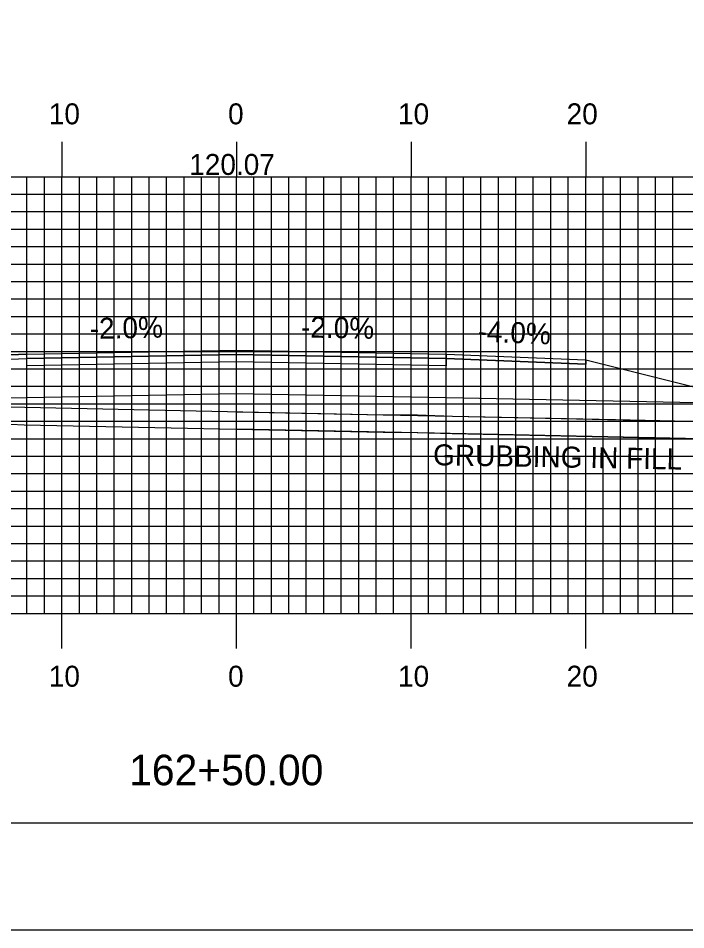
# Model space of a CAD drawing. Extents: x 1780680 to 1781023, y 442591 to 442811.
# Drawn here: x 1780832.9 to 1780871.1, y 442590.5 to 442642.7 of the extents above; entities that cross this region are included whole.
import ezdxf

# ---------------------------------------------------------------- set-up
doc = ezdxf.new("R2010")
doc.units = 0
for name, color, linetype in [('ANNOTATION', 7, 'Continuous'), ('BORDER', 7, 'Continuous'), ('D_Roadway_Centerline', 7, 'Continuous'), ('D_Roadway_Centerline_Text', 7, 'Continuous'), ('D_Roadway_Edge_Shoulder', 7, 'Continuous'), ('D_Roadway_Edge_TW', 7, 'Continuous'), ('D_Roadway_Pavement', 7, 'Continuous'), ('D_Roadway_SlopeLines', 7, 'Continuous'), ('D_Roadway_SubGrade', 7, 'Continuous'), ('GRUBBING IN FILL', 7, 'Continuous'), ('H_V ANNOTATION', 7, 'Continuous'), ('MAJOR', 7, 'Continuous'), ('MINOR', 7, 'Continuous'), ('PLOT BOUNDARY', 7, 'Continuous'), ('S_Roadway_Centerline', 7, 'Continuous')]:
    doc.layers.add(name, color=color, linetype=linetype)

msp = doc.modelspace()

# ---------------------------------------------------------------- linework, layer by layer
at = {"layer": 'BORDER'}
msp.add_lwpolyline([(1780695.782, 442596.665), (1781015.782, 442596.665), (1781015.782, 442806.665), (1780695.782, 442806.665)], close=True, dxfattribs=at)
at = {"layer": 'D_Roadway_Centerline'}
msp.add_lwpolyline([(1780799.726, 442621.091), (1780800.976, 442621.083), (1780802.226, 442621.017), (1780803.476, 442620.894), (1780804.726, 442620.714), (1780811.207, 442619.634), (1780815.207, 442620.634), (1780825.382, 442623.178), (1780833.382, 442623.498), (1780845.382, 442623.738), (1780857.382, 442623.498), (1780865.382, 442623.178), (1780875.556, 442620.634), (1780880.076, 442619.504)], dxfattribs=at)
at = {"layer": 'D_Roadway_Edge_Shoulder'}
for points in [[(1780833.382, 442623.498), (1780825.382, 442623.178), (1780825.382, 442622.928), (1780833.382, 442623.248)], [(1780857.382, 442623.498), (1780865.382, 442623.178), (1780865.382, 442622.928), (1780857.382, 442623.248)]]:
    msp.add_lwpolyline(points, close=True, dxfattribs=at)
at = {"layer": 'D_Roadway_Edge_TW'}
msp.add_lwpolyline([(1780833.382, 442623.248), (1780833.382, 442623.498), (1780845.382, 442623.738), (1780857.382, 442623.498), (1780857.382, 442623.248), (1780845.382, 442623.488)], close=True, dxfattribs=at)
at = {"layer": 'D_Roadway_Pavement'}
msp.add_lwpolyline([(1780833.382, 442622.831), (1780833.382, 442623.248), (1780845.382, 442623.488), (1780857.382, 442623.248), (1780857.382, 442622.831), (1780845.382, 442623.071)], close=True, dxfattribs=at)
at = {"layer": 'D_Roadway_SlopeLines'}
msp.add_lwpolyline([(1780865.382, 442623.178), (1780875.556, 442620.634), (1780880.076, 442619.504)], dxfattribs=at)
at = {"layer": 'D_Roadway_SubGrade'}
msp.add_lwpolyline([(1780833.382, 442620.998), (1780815.207, 442620.634), (1780825.382, 442623.178), (1780825.382, 442622.928), (1780833.382, 442623.248), (1780845.382, 442623.488), (1780857.382, 442623.248), (1780865.382, 442622.928), (1780865.382, 442623.178), (1780875.556, 442620.634), (1780857.382, 442620.998), (1780845.382, 442621.238)], close=True, dxfattribs=at)
at = {"layer": 'GRUBBING IN FILL'}
msp.add_lwpolyline([(1780815.207, 442620.095), (1780831.608, 442619.507), (1780832.443, 442619.493), (1780833.221, 442619.462), (1780853.776, 442619.036), (1780855.733, 442619.025), (1780857.728, 442618.957), (1780875.556, 442618.579)], dxfattribs=at)
msp.add_lwpolyline([(1780815.207, 442620.095), (1780831.608, 442619.507), (1780832.443, 442619.493), (1780833.221, 442619.462), (1780853.776, 442619.036), (1780855.733, 442619.025), (1780857.728, 442618.957), (1780875.556, 442618.579)], dxfattribs=at)
msp.add_lwpolyline([(1780875.556, 442618.579), (1780866.642, 442618.768), (1780856.731, 442618.991), (1780845.382, 442619.21), (1780845.382, 442620.21), (1780853.789, 442620.036), (1780857.756, 442619.957), (1780867.082, 442619.759), (1780875.556, 442619.58)], close=True, dxfattribs=at)
msp.add_lwpolyline([(1780875.556, 442618.579), (1780866.642, 442618.768), (1780856.731, 442618.991), (1780845.382, 442619.21), (1780845.382, 442620.21), (1780853.789, 442620.036), (1780857.756, 442619.957), (1780867.082, 442619.759), (1780875.556, 442619.58)], close=True, dxfattribs=at)
at = {"layer": 'MAJOR'}
for p, q in [((1780835.382, 442635.669), (1780835.382, 442633.665)), ((1780845.382, 442635.669), (1780845.382, 442633.665)), ((1780855.382, 442635.669), (1780855.382, 442633.665)), ((1780865.382, 442635.669), (1780865.382, 442633.665)), ((1780705.382, 442633.665), (1780985.382, 442633.665)), ((1780705.382, 442633.665), (1780985.382, 442633.665)), ((1780835.382, 442608.665), (1780835.382, 442633.665)), ((1780845.382, 442608.665), (1780845.382, 442633.665)), ((1780855.382, 442608.665), (1780855.382, 442633.665)), ((1780865.382, 442608.665), (1780865.382, 442633.665)), ((1780705.382, 442628.665), (1780985.382, 442628.665)), ((1780705.382, 442623.665), (1780985.382, 442623.665)), ((1780705.382, 442618.665), (1780985.382, 442618.665)), ((1780705.382, 442613.665), (1780985.382, 442613.665)), ((1780705.382, 442608.665), (1780985.382, 442608.665)), ((1780705.382, 442608.665), (1780985.382, 442608.665)), ((1780835.382, 442606.661), (1780835.382, 442608.665)), ((1780845.382, 442606.661), (1780845.382, 442608.665)), ((1780855.382, 442606.661), (1780855.382, 442608.665)), ((1780865.382, 442606.661), (1780865.382, 442608.665))]:
    msp.add_line(p, q, dxfattribs=at)
at = {"layer": 'MINOR'}
for p, q in [((1780833.382, 442608.665), (1780833.382, 442633.665)), ((1780834.382, 442608.665), (1780834.382, 442633.665)), ((1780836.382, 442608.665), (1780836.382, 442633.665)), ((1780837.382, 442608.665), (1780837.382, 442633.665)), ((1780838.382, 442608.665), (1780838.382, 442633.665)), ((1780839.382, 442608.665), (1780839.382, 442633.665)), ((1780840.382, 442608.665), (1780840.382, 442633.665)), ((1780841.382, 442608.665), (1780841.382, 442633.665)), ((1780842.382, 442608.665), (1780842.382, 442633.665)), ((1780843.382, 442608.665), (1780843.382, 442633.665)), ((1780844.382, 442608.665), (1780844.382, 442633.665)), ((1780846.382, 442608.665), (1780846.382, 442633.665)), ((1780847.382, 442608.665), (1780847.382, 442633.665)), ((1780848.382, 442608.665), (1780848.382, 442633.665)), ((1780849.382, 442608.665), (1780849.382, 442633.665)), ((1780850.382, 442608.665), (1780850.382, 442633.665)), ((1780851.382, 442608.665), (1780851.382, 442633.665)), ((1780852.382, 442608.665), (1780852.382, 442633.665)), ((1780853.382, 442608.665), (1780853.382, 442633.665)), ((1780854.382, 442608.665), (1780854.382, 442633.665)), ((1780856.382, 442608.665), (1780856.382, 442633.665)), ((1780857.382, 442608.665), (1780857.382, 442633.665)), ((1780858.382, 442608.665), (1780858.382, 442633.665)), ((1780859.382, 442608.665), (1780859.382, 442633.665)), ((1780860.382, 442608.665), (1780860.382, 442633.665)), ((1780861.382, 442608.665), (1780861.382, 442633.665)), ((1780862.382, 442608.665), (1780862.382, 442633.665)), ((1780863.382, 442608.665), (1780863.382, 442633.665)), ((1780864.382, 442608.665), (1780864.382, 442633.665)), ((1780866.382, 442608.665), (1780866.382, 442633.665)), ((1780867.382, 442608.665), (1780867.382, 442633.665)), ((1780868.382, 442608.665), (1780868.382, 442633.665)), ((1780869.382, 442608.665), (1780869.382, 442633.665)), ((1780870.382, 442608.665), (1780870.382, 442633.665)), ((1780705.382, 442632.665), (1780985.382, 442632.665)), ((1780705.382, 442631.665), (1780985.382, 442631.665)), ((1780705.382, 442630.665), (1780985.382, 442630.665)), ((1780705.382, 442629.665), (1780985.382, 442629.665)), ((1780705.382, 442627.665), (1780985.382, 442627.665)), ((1780705.382, 442626.665), (1780985.382, 442626.665)), ((1780705.382, 442625.665), (1780985.382, 442625.665)), ((1780705.382, 442624.665), (1780985.382, 442624.665)), ((1780705.382, 442622.665), (1780985.382, 442622.665)), ((1780705.382, 442621.665), (1780985.382, 442621.665)), ((1780705.382, 442620.665), (1780985.382, 442620.665)), ((1780705.382, 442619.665), (1780985.382, 442619.665)), ((1780705.382, 442617.665), (1780985.382, 442617.665)), ((1780705.382, 442616.665), (1780985.382, 442616.665)), ((1780705.382, 442615.665), (1780985.382, 442615.665)), ((1780705.382, 442614.665), (1780985.382, 442614.665)), ((1780705.382, 442612.665), (1780985.382, 442612.665)), ((1780705.382, 442611.665), (1780985.382, 442611.665)), ((1780705.382, 442610.665), (1780985.382, 442610.665)), ((1780705.382, 442609.665), (1780985.382, 442609.665))]:
    msp.add_line(p, q, dxfattribs=at)
at = {"layer": 'PLOT BOUNDARY'}
msp.add_lwpolyline([(1780679.595, 442590.547), (1781019.595, 442590.547), (1781019.595, 442810.547), (1780679.595, 442810.547)], close=True, dxfattribs=at)
at = {"layer": 'S_Roadway_Centerline'}
msp.add_lwpolyline([(1780776.028, 442621.586), (1780788.704, 442621.332), (1780794.623, 442621.011), (1780809.821, 442621.251), (1780810.607, 442621.261), (1780811.31, 442621.235), (1780831.635, 442620.506), (1780832.471, 442620.493), (1780833.251, 442620.462), (1780853.789, 442620.036), (1780855.753, 442620.025), (1780857.756, 442619.957), (1780876.408, 442619.562), (1780879.04, 442619.51), (1780881.97, 442619.494), (1780891.242, 442619.255), (1780899.314, 442619.056)], dxfattribs=at)

# ---------------------------------------------------------------- texts
at = {"layer": 'ANNOTATION'}
for s, rotation, p in [('-2.0%', 1.1458, (1780836.988, 442624.37)), ('-2.0%', 358.8542, (1780849.068, 442624.464)), ('-4.0%', 357.7094, (1780859.173, 442624.228))]:
    msp.add_text(s, height=1.2, rotation=rotation, dxfattribs=at).set_placement(p)
at = {"layer": 'D_Roadway_Centerline'}
for s, p in [('C', (1780845.376, 442623.738)), ('L', (1780845.382, 442623.73))]:
    msp.add_text(s, height=0.0146, dxfattribs=at).set_placement(p)
at = {"layer": 'D_Roadway_Centerline_Text'}
msp.add_text('120.07', height=1.2, dxfattribs=at).set_placement((1780842.674, 442633.768))
at = {"layer": 'GRUBBING IN FILL'}
msp.add_text('GRUBBING IN FILL', height=1.2, rotation=358.9728, dxfattribs=at).set_placement((1780856.634, 442617.15))
at = {"layer": 'H_V ANNOTATION'}
for s, height, p in [('10', 1.2, (1780834.632, 442636.665)), ('0', 1.2, (1780844.9, 442636.665)), ('10', 1.2, (1780854.632, 442636.665)), ('20', 1.2, (1780864.29, 442636.665)), ('10', 1.2, (1780834.632, 442604.465)), ('0', 1.2, (1780844.9, 442604.465)), ('10', 1.2, (1780854.632, 442604.465)), ('20', 1.2, (1780864.29, 442604.465)), ('162+50.00', 1.75, (1780839.233, 442598.821))]:
    msp.add_text(s, height=height, dxfattribs=at).set_placement(p)

doc.saveas('drawing.dxf')
